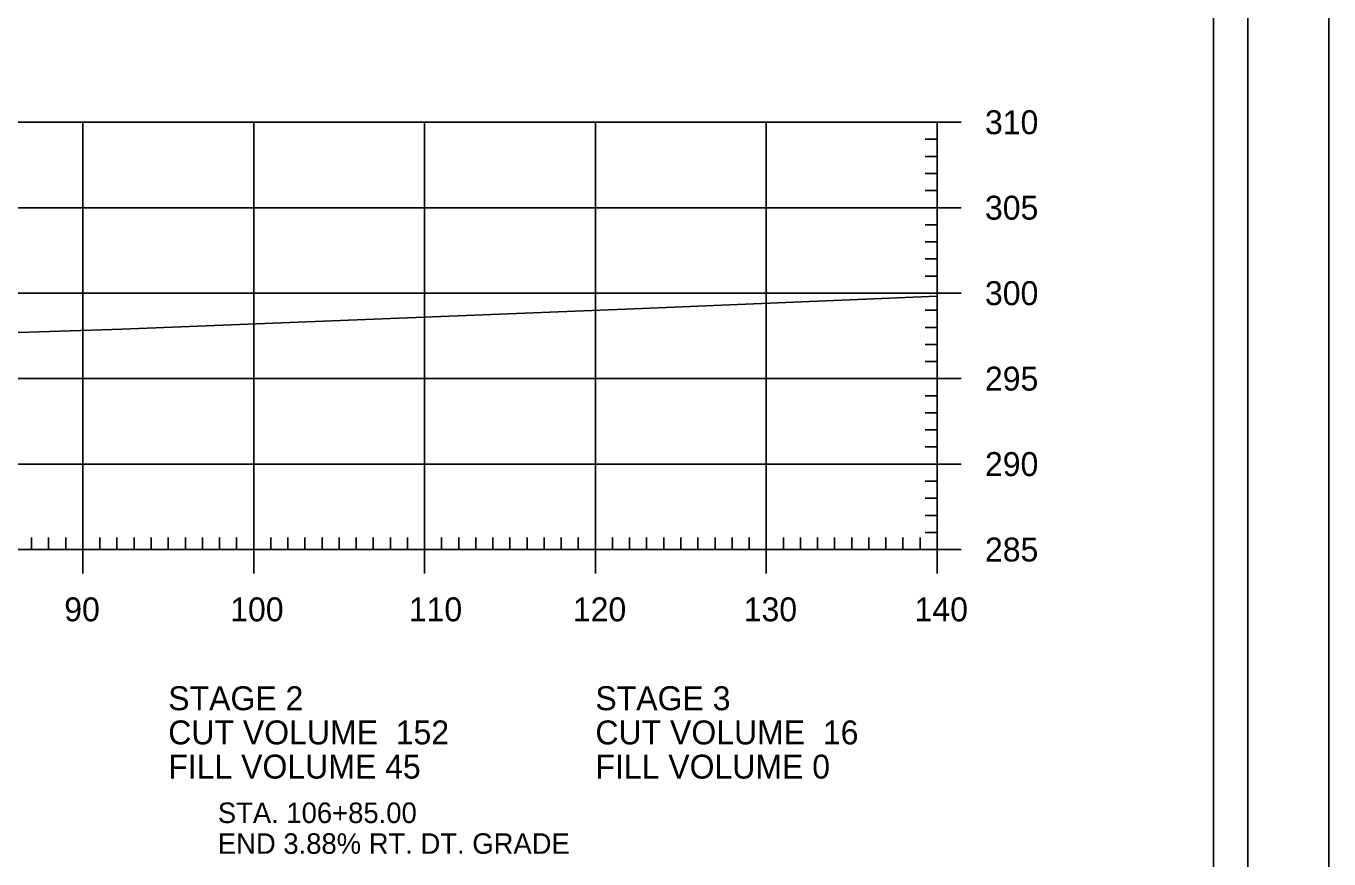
# Model space of a CAD drawing. Extents: x 1368713 to 1370673, y 380279 to 380950.
# Drawn here: x 1370239 to 1370315.2, y 380639.7 to 380688.4 of the extents above; entities that cross this region are included whole.
import ezdxf

# ---------------------------------------------------------------- set-up
doc = ezdxf.new("R2010")
doc.units = 0
for name, color, linetype in [('Notes', 7, 'Continuous'), ('R_Axis', 7, 'Continuous'), ('R_Axis Annot', 7, 'Continuous'), ('R_Border', 7, 'Continuous'), ('R_Exist Surface', 7, 'Continuous'), ('R_Grid', 7, 'Continuous'), ('R_No Plot', 7, 'Continuous')]:
    doc.layers.add(name, color=color, linetype=linetype)

msp = doc.modelspace()

# ---------------------------------------------------------------- linework, layer by layer
at = {"layer": 'R_Axis'}
for p, q in [((1370293.683, 380682.754), (1370290.883, 380682.754)), ((1370292.283, 380657.754), (1370292.283, 380682.754)), ((1370292.283, 380681.754), (1370291.583, 380681.754)), ((1370292.283, 380680.754), (1370291.583, 380680.754)), ((1370292.283, 380679.754), (1370291.583, 380679.754)), ((1370292.283, 380678.754), (1370291.583, 380678.754)), ((1370293.683, 380677.754), (1370290.883, 380677.754)), ((1370292.283, 380676.754), (1370291.583, 380676.754)), ((1370292.283, 380675.754), (1370291.583, 380675.754)), ((1370292.283, 380674.754), (1370291.583, 380674.754)), ((1370292.283, 380673.754), (1370291.583, 380673.754)), ((1370293.683, 380672.754), (1370290.883, 380672.754)), ((1370292.283, 380671.754), (1370291.583, 380671.754)), ((1370292.283, 380670.754), (1370291.583, 380670.754)), ((1370292.283, 380669.754), (1370291.583, 380669.754)), ((1370292.283, 380668.754), (1370291.583, 380668.754)), ((1370293.683, 380667.754), (1370290.883, 380667.754)), ((1370292.283, 380666.754), (1370291.583, 380666.754)), ((1370292.283, 380665.754), (1370291.583, 380665.754)), ((1370292.283, 380664.754), (1370291.583, 380664.754)), ((1370292.283, 380663.754), (1370291.583, 380663.754)), ((1370293.683, 380662.754), (1370290.883, 380662.754)), ((1370292.283, 380661.754), (1370291.583, 380661.754)), ((1370292.283, 380660.754), (1370291.583, 380660.754)), ((1370292.283, 380659.754), (1370291.583, 380659.754)), ((1370239.283, 380657.754), (1370239.283, 380658.454)), ((1370240.283, 380657.754), (1370240.283, 380658.454)), ((1370241.283, 380657.754), (1370241.283, 380658.454)), ((1370242.283, 380656.354), (1370242.283, 380659.154)), ((1370243.283, 380657.754), (1370243.283, 380658.454)), ((1370244.283, 380657.754), (1370244.283, 380658.454)), ((1370245.283, 380657.754), (1370245.283, 380658.454)), ((1370246.283, 380657.754), (1370246.283, 380658.454)), ((1370247.283, 380657.754), (1370247.283, 380658.454)), ((1370248.283, 380657.754), (1370248.283, 380658.454)), ((1370249.283, 380657.754), (1370249.283, 380658.454)), ((1370250.283, 380657.754), (1370250.283, 380658.454)), ((1370251.283, 380657.754), (1370251.283, 380658.454)), ((1370252.283, 380656.354), (1370252.283, 380659.154)), ((1370253.283, 380657.754), (1370253.283, 380658.454)), ((1370254.283, 380657.754), (1370254.283, 380658.454)), ((1370255.283, 380657.754), (1370255.283, 380658.454)), ((1370256.283, 380657.754), (1370256.283, 380658.454)), ((1370257.283, 380657.754), (1370257.283, 380658.454)), ((1370258.283, 380657.754), (1370258.283, 380658.454)), ((1370259.283, 380657.754), (1370259.283, 380658.454)), ((1370260.283, 380657.754), (1370260.283, 380658.454)), ((1370261.283, 380657.754), (1370261.283, 380658.454)), ((1370262.283, 380656.354), (1370262.283, 380659.154)), ((1370263.283, 380657.754), (1370263.283, 380658.454)), ((1370264.283, 380657.754), (1370264.283, 380658.454)), ((1370265.283, 380657.754), (1370265.283, 380658.454)), ((1370266.283, 380657.754), (1370266.283, 380658.454)), ((1370267.283, 380657.754), (1370267.283, 380658.454)), ((1370268.283, 380657.754), (1370268.283, 380658.454)), ((1370269.283, 380657.754), (1370269.283, 380658.454)), ((1370270.283, 380657.754), (1370270.283, 380658.454)), ((1370271.283, 380657.754), (1370271.283, 380658.454)), ((1370272.283, 380656.354), (1370272.283, 380659.154)), ((1370273.283, 380657.754), (1370273.283, 380658.454)), ((1370274.283, 380657.754), (1370274.283, 380658.454)), ((1370275.283, 380657.754), (1370275.283, 380658.454)), ((1370276.283, 380657.754), (1370276.283, 380658.454)), ((1370277.283, 380657.754), (1370277.283, 380658.454)), ((1370278.283, 380657.754), (1370278.283, 380658.454)), ((1370279.283, 380657.754), (1370279.283, 380658.454)), ((1370280.283, 380657.754), (1370280.283, 380658.454)), ((1370281.283, 380657.754), (1370281.283, 380658.454)), ((1370282.283, 380656.354), (1370282.283, 380659.154)), ((1370283.283, 380657.754), (1370283.283, 380658.454)), ((1370284.283, 380657.754), (1370284.283, 380658.454)), ((1370285.283, 380657.754), (1370285.283, 380658.454)), ((1370286.283, 380657.754), (1370286.283, 380658.454)), ((1370287.283, 380657.754), (1370287.283, 380658.454)), ((1370288.283, 380657.754), (1370288.283, 380658.454)), ((1370289.283, 380657.754), (1370289.283, 380658.454)), ((1370290.283, 380657.754), (1370290.283, 380658.454)), ((1370291.283, 380657.754), (1370291.283, 380658.454)), ((1370292.283, 380658.754), (1370291.583, 380658.754)), ((1370292.283, 380656.354), (1370292.283, 380659.154)), ((1370012.283, 380657.754), (1370292.283, 380657.754)), ((1370293.683, 380657.754), (1370290.883, 380657.754))]:
    msp.add_line(p, q, dxfattribs=at)
at = {"layer": 'R_Border'}
msp.add_line((1370310.463, 380527.754), (1370310.463, 380733.214), dxfattribs=at)
at = {"layer": 'R_Exist Surface'}
msp.add_lwpolyline([(1370237.274, 380670.416), (1370244.579, 380670.646), (1370275.022, 380671.855), (1370292.283, 380672.578)], dxfattribs=at)
at = {"layer": 'R_Grid'}
for p, q in [((1370012.283, 380682.754), (1370292.283, 380682.754)), ((1370242.283, 380657.754), (1370242.283, 380682.754)), ((1370252.283, 380657.754), (1370252.283, 380682.754)), ((1370262.283, 380657.754), (1370262.283, 380682.754)), ((1370272.283, 380657.754), (1370272.283, 380682.754)), ((1370282.283, 380657.754), (1370282.283, 380682.754)), ((1370292.283, 380657.754), (1370292.283, 380682.754)), ((1370012.283, 380677.754), (1370292.283, 380677.754)), ((1370012.283, 380672.754), (1370292.283, 380672.754)), ((1370012.283, 380667.754), (1370292.283, 380667.754)), ((1370012.283, 380662.754), (1370292.283, 380662.754)), ((1370012.283, 380657.754), (1370292.283, 380657.754))]:
    msp.add_line(p, q, dxfattribs=at)
at = {"layer": 'R_No Plot'}
for points in [[(1369981.875, 380737.108), (1370315.215, 380737.108), (1370315.215, 380523.771), (1369981.875, 380523.771)], [(1370308.463, 380632.484), (1369996.283, 380632.484), (1369996.283, 380731.214), (1370245.823, 380731.214), (1370245.823, 380721.334), (1370263.363, 380721.334), (1370287.463, 380721.334), (1370287.463, 380699.001), (1370308.463, 380699.001)], [(1369996.283, 380731.214), (1370245.823, 380731.214), (1370245.823, 380721.334), (1370263.363, 380721.334), (1370287.463, 380721.334), (1370287.463, 380699.001), (1370308.463, 380699.001), (1370308.463, 380529.754), (1369996.283, 380529.754)]]:
    msp.add_lwpolyline(points, close=True, dxfattribs=at)

# ---------------------------------------------------------------- texts
at = {"layer": 'Notes'}
for s, p in [('STA. 106+85.00', (1370250.186, 380641.752)), ('END 3.88% RT. DT. GRADE', (1370250.186, 380639.952))]:
    msp.add_text(s, height=1.2, dxfattribs=at).set_placement(p)
at = {"layer": 'R_Axis Annot'}
for s, p in [('310', (1370295.083, 380682.054)), ('305', (1370295.083, 380677.054)), ('300', (1370295.083, 380672.054)), ('295', (1370295.083, 380667.054)), ('290', (1370295.083, 380662.054)), ('285', (1370295.083, 380657.054)), ('90', (1370241.197, 380653.554)), ('100', (1370250.91, 380653.554)), ('110', (1370261.362, 380653.554)), ('120', (1370270.965, 380653.554)), ('130', (1370280.965, 380653.554)), ('140', (1370290.965, 380653.554)), ('STAGE 2', (1370247.283, 380648.354)), ('STAGE 3', (1370272.283, 380648.354)), ('CUT VOLUME  152', (1370247.283, 380646.354)), ('CUT VOLUME  16', (1370272.283, 380646.354)), ('FILL VOLUME 45', (1370247.283, 380644.354)), ('FILL VOLUME 0', (1370272.283, 380644.354))]:
    msp.add_text(s, height=1.4, dxfattribs=at).set_placement(p)

doc.saveas('drawing.dxf')
